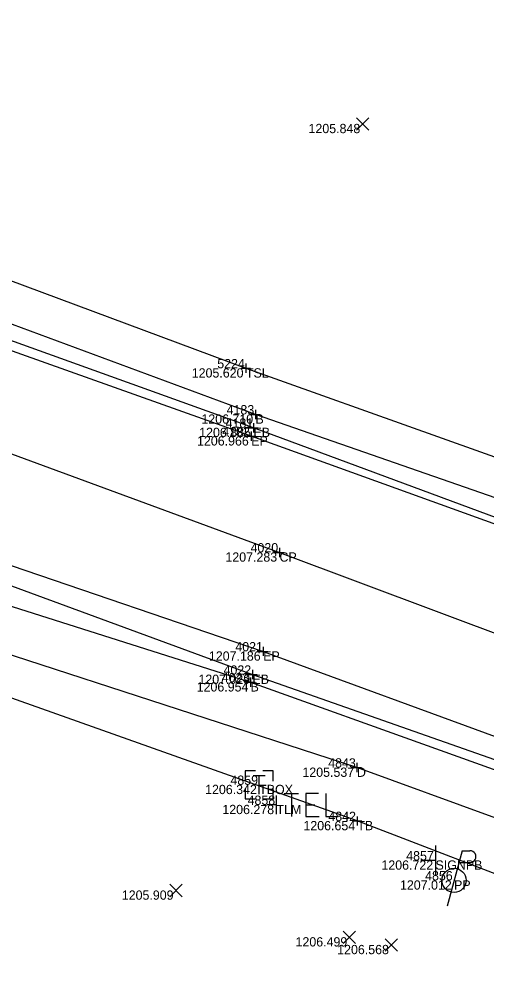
# Model space of a CAD drawing. Extents: x 2044996 to 2050343, y 455232 to 458054.
# Drawn here: x 2047693.5 to 2047743.9, y 456915.7 to 457018.9 of the extents above; entities that cross this region are included whole.
import ezdxf

# ---------------------------------------------------------------- set-up
doc = ezdxf.new("R2010")
doc.units = 0
for name, color, linetype in [('DR_X_Ditch', 7, 'Continuous'), ('DT_X_Contour_Minor', 7, 'Continuous'), ('DT_X_Contour_Text', 7, 'Continuous'), ('DT_X_Spot_Elev', 7, 'Continuous'), ('DT_X_TIN_Hull', 7, 'Continuous'), ('DT_X_Triangles', 7, 'Continuous'), ('DT_X_Void', 7, 'Continuous'), ('PV_X_COP', 7, 'Continuous'), ('PV_X_EOP', 7, 'Continuous'), ('PV_X_Shoulder_Aggregate', 7, 'Continuous'), ('SN_X_Public', 7, 'Continuous'), ('SV_X_Break_Lines', 7, 'Continuous'), ('SV_X_Toe_of_Slope', 7, 'Continuous'), ('SV_X_Top_of_Bank', 7, 'Continuous'), ('UT_X_Electric_Cells', 7, 'Continuous')]:
    doc.layers.add(name, color=color, linetype=linetype)

msp = doc.modelspace()

# ---------------------------------------------------------------- linework, layer by layer
at = {"layer": 'DR_X_Ditch'}
msp.add_lwpolyline([(2047944.96, 456861.76), (2047899.25, 456878.16), (2047861.64, 456891.96), (2047815.35, 456909.09), (2047774.86, 456921.86), (2047729.93, 456938.25), (2047691.42, 456950.76), (2047669.22, 456956.37), (2047658.75, 456950.98), (2047651.4, 456909.49), (2047651.98, 456861.4), (2047653.43, 456816.89), (2047656.94, 456761.43), (2047657.83, 456718.94), (2047659.36, 456677.43), (2047660.77, 456628.12), (2047661.37, 456577.1), (2047662.68, 456519.59), (2047665.25, 456466.46), (2047666.16, 456418.54), (2047665.56, 456406.95)], dxfattribs=at)
at = {"layer": 'DT_X_Spot_Elev'}
for p, q in [((2047729.88, 457006.98), (2047731.21, 457008.32)), ((2047729.88, 457008.32), (2047731.21, 457006.98)), ((2047709.74, 456924.33), (2047711.07, 456925.67)), ((2047709.74, 456925.67), (2047711.07, 456924.33)), ((2047728.46, 456919.29), (2047729.79, 456920.62)), ((2047728.46, 456920.62), (2047729.79, 456919.29)), ((2047732.97, 456918.47), (2047734.31, 456919.8)), ((2047732.97, 456919.8), (2047734.31, 456918.47))]:
    msp.add_line(p, q, dxfattribs=at)
at = {"layer": 'DT_X_TIN_Hull'}
for p, q in [((2047718.74, 456937.39), (2047720.04, 456937.39)), ((2047719.39, 456935.39), (2047719.39, 456937.39)), ((2047719.39, 456936.39), (2047719.39, 456936.39)), ((2047721.26, 456933.23), (2047721.26, 456935.23)), ((2047721.26, 456934.23), (2047720.26, 456934.23))]:
    msp.add_line(p, q, dxfattribs=at)
for points in [[(2047718.99, 456937.89), (2047717.89, 456937.89), (2047717.89, 456936.79)], [(2047720.89, 456936.79), (2047720.89, 456937.89), (2047719.79, 456937.89)], [(2047717.89, 456935.99), (2047717.89, 456934.89), (2047718.99, 456934.89)], [(2047719.79, 456934.89), (2047720.89, 456934.89), (2047720.89, 456935.99)], [(2047722.07, 456935.47), (2047723.63, 456935.47)], [(2047722.86, 456935.47), (2047722.86, 456932.97)], [(2047725.77, 456935.47), (2047724.41, 456935.47), (2047724.41, 456932.97), (2047725.87, 456932.97)], [(2047726.56, 456935.47), (2047726.56, 456932.97), (2047727.92, 456932.97)], [(2047724.41, 456934.23), (2047725.38, 456934.23)]]:
    msp.add_lwpolyline(points, dxfattribs=at)
at = {"layer": 'DT_X_Void'}
for p, q in [((2047717.46, 456981.3), (2047718.46, 456981.3)), ((2047717.96, 456981.8), (2047717.96, 456980.8)), ((2047717.96, 456981.3), (2047717.96, 456981.3)), ((2047718.49, 456976.33), (2047719.49, 456976.33)), ((2047718.99, 456976.83), (2047718.99, 456975.83)), ((2047718.99, 456976.33), (2047718.99, 456976.33)), ((2047718.27, 456974.89), (2047719.27, 456974.89)), ((2047718.77, 456975.39), (2047718.77, 456974.39)), ((2047718.77, 456974.89), (2047718.77, 456974.89)), ((2047718.03, 456973.97), (2047719.03, 456973.97)), ((2047718.53, 456974.47), (2047718.53, 456973.47)), ((2047718.53, 456973.97), (2047718.53, 456973.97)), ((2047721.08, 456961.45), (2047722.08, 456961.45)), ((2047721.58, 456961.95), (2047721.58, 456960.95)), ((2047721.58, 456961.45), (2047721.58, 456961.45)), ((2047719.82, 456951.28), (2047719.82, 456950.28)), ((2047719.32, 456950.78), (2047720.32, 456950.78)), ((2047719.82, 456950.78), (2047719.82, 456950.78)), ((2047718.16, 456948.27), (2047719.16, 456948.27)), ((2047718.66, 456948.77), (2047718.66, 456947.77)), ((2047718.66, 456948.27), (2047718.66, 456948.27)), ((2047717.96, 456947.45), (2047718.96, 456947.45)), ((2047718.46, 456947.95), (2047718.46, 456946.95)), ((2047718.46, 456947.45), (2047718.46, 456947.45)), ((2047729.93, 456938.75), (2047729.93, 456937.75)), ((2047729.43, 456938.25), (2047730.43, 456938.25)), ((2047729.93, 456938.25), (2047729.93, 456938.25)), ((2047729.97, 456932.99), (2047729.97, 456931.99)), ((2047729.47, 456932.49), (2047730.47, 456932.49)), ((2047729.97, 456932.49), (2047729.97, 456932.49))]:
    msp.add_line(p, q, dxfattribs=at)
at = {"layer": 'PV_X_COP'}
msp.add_lwpolyline([(2047648.6, 456988.51), (2047681.61, 456976.15), (2047721.58, 456961.45), (2047764.11, 456945.53)], dxfattribs=at)
at = {"layer": 'PV_X_EOP'}
for p, q in [((2047718.53, 456973.97), (2047683.07, 456986.61)), ((2047765.19, 456957.15), (2047718.53, 456973.97)), ((2047677.77, 456965.09), (2047719.82, 456950.78)), ((2047719.82, 456950.78), (2047760.28, 456935.93))]:
    msp.add_line(p, q, dxfattribs=at)
at = {"layer": 'PV_X_Shoulder_Aggregate'}
for points in [[(2047765.41, 456957.6), (2047718.77, 456974.89), (2047683.47, 456987.55), (2047664.01, 456996.43), (2047655.41, 457004.2), (2047650.14, 457012.19), (2047644.76, 457024.2), (2047643.27, 457033.33), (2047642.36, 457078.68), (2047641.18, 457122.01), (2047640.21, 457169.15), (2047639.13, 457212.34), (2047637.97, 457261.48), (2047636.93, 457312.89), (2047635.93, 457367.47)], [(2047651.94, 456638.93), (2047650.86, 456688.18), (2047649.6, 456733), (2047648.37, 456778.91), (2047647.51, 456826.93), (2047646.86, 456872.4), (2047645.87, 456917.72), (2047645.01, 456938.98), (2047644.95, 456952.82), (2047645.89, 456959.85), (2047646.68, 456960.97), (2047650.24, 456962.76), (2047655.73, 456966.3), (2047657.7, 456966.84), (2047664.7, 456965.75), (2047672.59, 456964.54), (2047677.71, 456963.33), (2047718.66, 456948.27), (2047759.49, 456933.93)]]:
    msp.add_lwpolyline(points, dxfattribs=at)
at = {"layer": 'SN_X_Public'}
for p, q in [((2047738.4, 456929.84), (2047738.4, 456926.64)), ((2047738.4, 456928.24), (2047736.8, 456928.24))]:
    msp.add_line(p, q, dxfattribs=at)
at = {"layer": 'SV_X_Break_Lines'}
for points in [[(2047766.63, 456959.74), (2047718.99, 456976.33), (2047684.01, 456989.24), (2047664.81, 456998.06), (2047657.38, 457005.81), (2047652.26, 457013.72), (2047648.31, 457024.57), (2047646.23, 457034.09), (2047644.07, 457078.24), (2047642.74, 457121.94), (2047641.84, 457169.12), (2047640.7, 457212.33), (2047639.26, 457261.64), (2047638.13, 457312.9), (2047637.8, 457367.1)], [(2047652.8, 456955.87), (2047664.54, 456962.83), (2047671.52, 456961.88), (2047676.87, 456960.65), (2047718.46, 456947.45), (2047759.36, 456932.8), (2047800.99, 456917.68), (2047842.23, 456903.25), (2047882.81, 456888.44), (2047923.67, 456874.28), (2047947.96, 456864.48)]]:
    msp.add_lwpolyline(points, dxfattribs=at)
at = {"layer": 'SV_X_Toe_of_Slope'}
msp.add_lwpolyline([(2047656.35, 457022.83), (2047660.05, 457013.16), (2047664.41, 457005.04), (2047675.76, 456997.03), (2047717.96, 456981.3), (2047760.28, 456966.23)], dxfattribs=at)
at = {"layer": 'SV_X_Top_of_Bank'}
msp.add_lwpolyline([(2047942.14, 456857.99), (2047898.01, 456872.36), (2047859.06, 456885.19), (2047815.47, 456901.27), (2047771.85, 456916.42), (2047729.97, 456932.49), (2047688.22, 456947.3), (2047669.99, 456955.17), (2047661.07, 456948.62), (2047656.72, 456911.9), (2047659.76, 456864.17), (2047662.28, 456815.7), (2047662.72, 456763.39), (2047662.48, 456719.38), (2047665.2, 456677.14), (2047665.7, 456629.87), (2047667.28, 456578.15), (2047668.69, 456520.88), (2047669.88, 456466.8), (2047671, 456408.28)], dxfattribs=at)
at = {"layer": 'UT_X_Electric_Cells'}
for p, q in [((2047741.26, 456929.29), (2047739.65, 456923.29)), ((2047741.26, 456929.29), (2047742.11, 456929.29)), ((2047740.91, 456928.02), (2047742.11, 456928.02))]:
    msp.add_line(p, q, dxfattribs=at)
msp.add_circle((2047740.4, 456926.09), 1.3, dxfattribs=at)
msp.add_arc((2047742.12, 456928.65), 0.638, 268.8767, 91.1233, dxfattribs=at)

# ---------------------------------------------------------------- texts
at = {"layer": 'DT_X_Contour_Minor'}
for s, p in [('1205.848', (2047724.71, 457006.65)), ('1205.620', (2047712.12, 456980.3)), ('1206.710', (2047713.16, 456975.33)), ('1206.885', (2047712.92, 456973.89)), ('1206.966', (2047712.69, 456972.97)), ('1207.283', (2047715.75, 456960.45)), ('1207.186', (2047713.97, 456949.78)), ('1207.029', (2047712.84, 456947.27)), ('1206.954', (2047712.65, 456946.45)), ('1205.537', (2047724.05, 456937.25)), ('1206.342', (2047713.56, 456935.39)), ('1206.278', (2047715.42, 456933.23)), ('1206.654', (2047724.16, 456931.49)), ('1206.722', (2047732.57, 456927.24)), ('1207.012', (2047734.57, 456925.09)), ('1205.909', (2047704.58, 456924)), ('1206.499', (2047723.31, 456918.96)), ('1206.568', (2047727.8, 456918.13))]:
    msp.add_text(s, height=1, dxfattribs=at).set_placement(p)
at = {"layer": 'DT_X_Contour_Text'}
for s, p in [('TSL', (2047717.96, 456980.3)), ('B', (2047718.99, 456975.33)), ('EB', (2047718.77, 456973.89)), ('EP', (2047718.53, 456972.97)), ('CP', (2047721.58, 456960.45)), ('EP', (2047719.82, 456949.78)), ('EB', (2047718.66, 456947.27)), ('B', (2047718.46, 456946.45)), ('D', (2047729.93, 456937.25)), ('TBOX', (2047719.39, 456935.39)), ('TLM', (2047721.26, 456933.23)), ('TB', (2047729.97, 456931.49)), ('SIGNPB', (2047738.4, 456927.24)), ('PP', (2047740.4, 456925.09))]:
    msp.add_text(s, height=1, dxfattribs=at).set_placement(p)
at = {"layer": 'DT_X_Triangles'}
for s, p in [('5224', (2047714.87, 456981.3)), ('4183', (2047715.88, 456976.33)), ('4181', (2047715.77, 456974.89)), ('4182', (2047715.41, 456973.97)), ('4020', (2047718.46, 456961.45)), ('4021', (2047716.82, 456950.78)), ('4022', (2047715.55, 456948.27)), ('4023', (2047715.35, 456947.45)), ('4843', (2047726.83, 456938.25)), ('4859', (2047716.29, 456936.39)), ('4858', (2047718.14, 456934.23)), ('4842', (2047726.85, 456932.49)), ('4857', (2047735.24, 456928.24)), ('4856', (2047737.28, 456926.09))]:
    msp.add_text(s, height=1, dxfattribs=at).set_placement(p)

doc.saveas('drawing.dxf')
